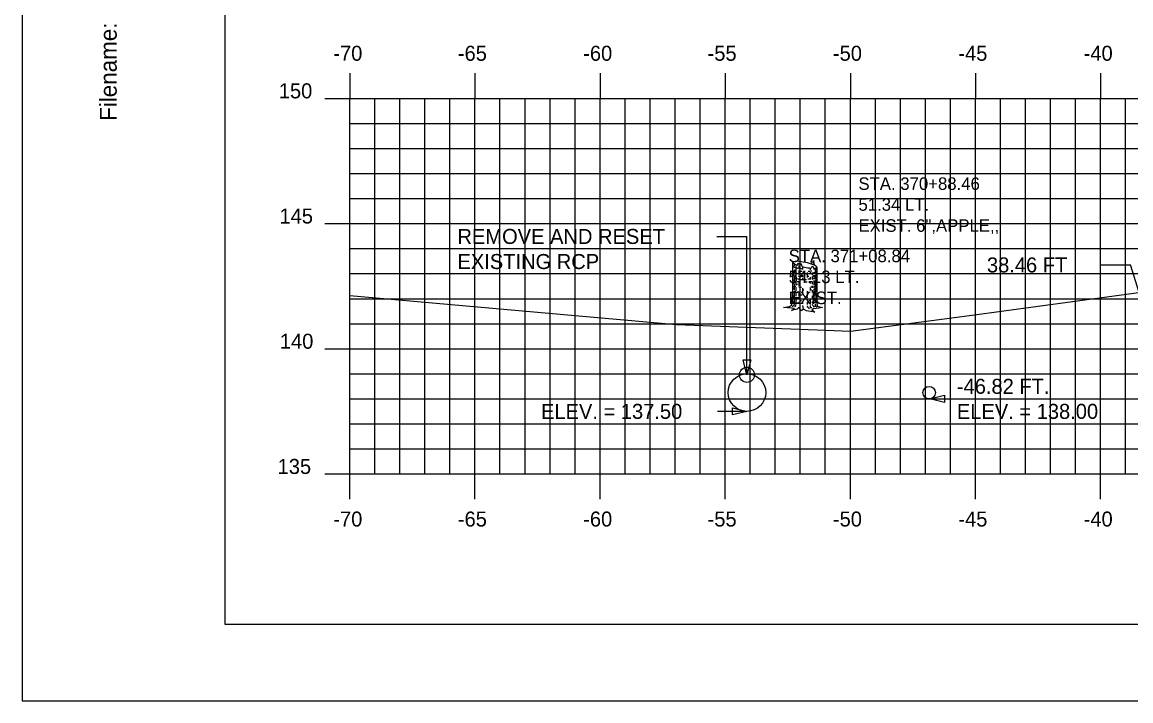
# Model space of a CAD drawing. Extents: x 1148299 to 1148469, y 608981 to 609091.
# Drawn here: x 1148298.63 to 1148342.93, y 608981.28 to 609008.38 of the extents above; entities that cross this region are included whole.
import ezdxf

# ---------------------------------------------------------------- set-up
doc = ezdxf.new("R2010")
doc.units = 0
for name, color, linetype in [('ANNOTATION', 7, 'Continuous'), ('BORDER', 7, 'Continuous'), ('D_Drainage_Culvert', 7, 'Continuous'), ('D_Text_Monospaced', 7, 'Continuous'), ('D_Text_Standard', 7, 'Continuous'), ('H_V ANNOTATION', 7, 'Continuous'), ('MAJOR', 7, 'Continuous'), ('MINOR', 7, 'Continuous'), ('PLOT BOUNDARY', 7, 'Continuous'), ('S_Drainage_Invert', 7, 'Continuous'), ('S_Roadway_Centerline', 7, 'Continuous'), ('S_Trees_Decid_NonPay', 7, 'Continuous')]:
    doc.layers.add(name, color=color, linetype=linetype)

msp = doc.modelspace()

# ---------------------------------------------------------------- linework, layer by layer
at = {"layer": 'ANNOTATION'}
for p, q in [((1148326.393, 608999.82), (1148327.593, 608999.82)), ((1148327.593, 608994.294), (1148327.593, 608999.82)), ((1148341.723, 608998.682), (1148342.923, 608998.682)), ((1148343.264, 608997.583), (1148342.923, 608998.682))]:
    msp.add_line(p, q, dxfattribs=at)
msp.add_lwpolyline([(1148327.743, 608994.894), (1148327.593, 608994.294), (1148327.443, 608994.894)], close=True, dxfattribs=at)
at = {"layer": 'BORDER'}
msp.add_lwpolyline([(1148306.724, 608984.335), (1148466.724, 608984.335), (1148466.724, 609089.335), (1148306.724, 609089.335)], close=True, dxfattribs=at)
at = {"layer": 'D_Drainage_Culvert'}
for centre, radius in [((1148327.593, 608993.585), 0.75), ((1148334.873, 608993.583), 0.25)]:
    msp.add_circle(centre, radius, dxfattribs=at)
at = {"layer": 'D_Text_Standard'}
msp.add_line((1148335.982, 608993.335), (1148340.686, 608993.335), dxfattribs=at)
for points in [[(1148334.904, 608993.335), (1148335.486, 608993.481), (1148335.486, 608993.19)], [(1148327.593, 608992.835), (1148327.011, 608992.69), (1148327.011, 608992.981)]]:
    msp.add_lwpolyline(points, close=True, dxfattribs=at)
for points in [[(1148334.904, 608993.335), (1148335.302, 608993.335), (1148335.982, 608993.335)], [(1148327.593, 608992.835), (1148327.091, 608992.835), (1148326.411, 608992.835)]]:
    msp.add_lwpolyline(points, dxfattribs=at)
at = {"layer": 'MAJOR'}
for p, q in [((1148311.724, 609006.337), (1148311.724, 609005.335)), ((1148316.724, 609006.337), (1148316.724, 609005.335)), ((1148321.724, 609006.337), (1148321.724, 609005.335)), ((1148326.724, 609006.337), (1148326.724, 609005.335)), ((1148331.724, 609006.337), (1148331.724, 609005.335)), ((1148336.724, 609006.337), (1148336.724, 609005.335)), ((1148341.724, 609006.337), (1148341.724, 609005.335)), ((1148310.722, 609005.335), (1148311.724, 609005.335)), ((1148311.724, 609005.335), (1148451.724, 609005.335)), ((1148311.724, 608990.335), (1148311.724, 609005.335)), ((1148311.724, 608990.335), (1148311.724, 609005.335)), ((1148311.724, 609005.335), (1148451.724, 609005.335)), ((1148316.724, 608990.335), (1148316.724, 609005.335)), ((1148321.724, 608990.335), (1148321.724, 609005.335)), ((1148326.724, 608990.335), (1148326.724, 609005.335)), ((1148331.724, 608990.335), (1148331.724, 609005.335)), ((1148336.724, 608990.335), (1148336.724, 609005.335)), ((1148341.724, 608990.335), (1148341.724, 609005.335)), ((1148310.722, 609000.335), (1148311.724, 609000.335)), ((1148311.724, 609000.335), (1148451.724, 609000.335)), ((1148310.722, 608995.335), (1148311.724, 608995.335)), ((1148311.724, 608995.335), (1148451.724, 608995.335)), ((1148310.722, 608990.335), (1148311.724, 608990.335)), ((1148311.724, 608990.335), (1148451.724, 608990.335)), ((1148311.724, 608990.335), (1148451.724, 608990.335)), ((1148311.724, 608989.333), (1148311.724, 608990.335)), ((1148316.724, 608989.333), (1148316.724, 608990.335)), ((1148321.724, 608989.333), (1148321.724, 608990.335)), ((1148326.724, 608989.333), (1148326.724, 608990.335)), ((1148331.724, 608989.333), (1148331.724, 608990.335)), ((1148336.724, 608989.333), (1148336.724, 608990.335)), ((1148341.724, 608989.333), (1148341.724, 608990.335))]:
    msp.add_line(p, q, dxfattribs=at)
at = {"layer": 'MINOR'}
for p, q in [((1148312.724, 608990.335), (1148312.724, 609005.335)), ((1148313.724, 608990.335), (1148313.724, 609005.335)), ((1148314.724, 608990.335), (1148314.724, 609005.335)), ((1148315.724, 608990.335), (1148315.724, 609005.335)), ((1148317.724, 608990.335), (1148317.724, 609005.335)), ((1148318.724, 608990.335), (1148318.724, 609005.335)), ((1148319.724, 608990.335), (1148319.724, 609005.335)), ((1148320.724, 608990.335), (1148320.724, 609005.335)), ((1148322.724, 608990.335), (1148322.724, 609005.335)), ((1148323.724, 608990.335), (1148323.724, 609005.335)), ((1148324.724, 608990.335), (1148324.724, 609005.335)), ((1148325.724, 608990.335), (1148325.724, 609005.335)), ((1148327.724, 608990.335), (1148327.724, 609005.335)), ((1148328.724, 608990.335), (1148328.724, 609005.335)), ((1148329.724, 608990.335), (1148329.724, 609005.335)), ((1148330.724, 608990.335), (1148330.724, 609005.335)), ((1148332.724, 608990.335), (1148332.724, 609005.335)), ((1148333.724, 608990.335), (1148333.724, 609005.335)), ((1148334.724, 608990.335), (1148334.724, 609005.335)), ((1148335.724, 608990.335), (1148335.724, 609005.335)), ((1148337.724, 608990.335), (1148337.724, 609005.335)), ((1148338.724, 608990.335), (1148338.724, 609005.335)), ((1148339.724, 608990.335), (1148339.724, 609005.335)), ((1148340.724, 608990.335), (1148340.724, 609005.335)), ((1148342.724, 608990.335), (1148342.724, 609005.335)), ((1148311.724, 609004.335), (1148451.724, 609004.335)), ((1148311.724, 609004.335), (1148312.726, 609004.335)), ((1148311.724, 609003.335), (1148451.724, 609003.335)), ((1148311.724, 609003.335), (1148312.726, 609003.335)), ((1148311.724, 609002.335), (1148451.724, 609002.335)), ((1148311.724, 609002.335), (1148312.726, 609002.335)), ((1148311.724, 609001.335), (1148451.724, 609001.335)), ((1148311.724, 609001.335), (1148312.726, 609001.335)), ((1148311.724, 608999.335), (1148451.724, 608999.335)), ((1148311.724, 608999.335), (1148312.726, 608999.335)), ((1148311.724, 608998.335), (1148451.724, 608998.335)), ((1148311.724, 608998.335), (1148312.726, 608998.335)), ((1148311.724, 608997.335), (1148451.724, 608997.335)), ((1148311.724, 608997.335), (1148312.726, 608997.335)), ((1148311.724, 608996.335), (1148451.724, 608996.335)), ((1148311.724, 608996.335), (1148312.726, 608996.335)), ((1148311.724, 608994.335), (1148451.724, 608994.335)), ((1148311.724, 608994.335), (1148312.726, 608994.335)), ((1148311.724, 608993.335), (1148451.724, 608993.335)), ((1148311.724, 608993.335), (1148312.726, 608993.335)), ((1148311.724, 608992.335), (1148451.724, 608992.335)), ((1148311.724, 608992.335), (1148312.726, 608992.335)), ((1148311.724, 608991.335), (1148451.724, 608991.335)), ((1148311.724, 608991.335), (1148312.726, 608991.335))]:
    msp.add_line(p, q, dxfattribs=at)
at = {"layer": 'PLOT BOUNDARY'}
msp.add_lwpolyline([(1148298.63, 608981.276), (1148468.63, 608981.276), (1148468.63, 609091.276), (1148298.63, 609091.276)], close=True, dxfattribs=at)
at = {"layer": 'S_Drainage_Invert'}
msp.add_circle((1148327.593, 608994.294), 0.3, dxfattribs=at)
at = {"layer": 'S_Roadway_Centerline'}
msp.add_lwpolyline([(1148311.724, 608997.456), (1148324.779, 608996.299), (1148330.75, 608996.073), (1148331.736, 608996.041), (1148336.482, 608996.659), (1148343.351, 608997.595), (1148346.718, 608997.619), (1148353.827, 608997.677), (1148359.018, 608997.725), (1148361.738, 608997.751), (1148365.941, 608997.793), (1148381.74, 608997.946), (1148386.77, 608997.817), (1148393.486, 608997.801)], dxfattribs=at)
at = {"layer": 'S_Trees_Decid_NonPay'}
for p, q in [((1148329.483, 608998.729), (1148329.483, 608998.634)), ((1148329.67, 608998.659), (1148329.67, 608998.511)), ((1148329.483, 608998.408), (1148329.483, 608998.325)), ((1148329.483, 608998.255), (1148329.483, 608998.004)), ((1148329.551, 608998.642), (1148329.551, 608998.341)), ((1148329.551, 608998.313), (1148329.551, 608998.181)), ((1148329.67, 608998.463), (1148329.67, 608998.294)), ((1148329.817, 608998.613), (1148329.817, 608998.506)), ((1148329.817, 608998.278), (1148329.817, 608998.191)), ((1148329.997, 608998.377), (1148329.997, 608998.177)), ((1148330.114, 608998.561), (1148330.114, 608998.482)), ((1148330.114, 608998.395), (1148330.114, 608998.311)), ((1148330.201, 608998.377), (1148330.201, 608998.29)), ((1148330.201, 608998.22), (1148330.201, 608998.099)), ((1148330.272, 608998.55), (1148330.272, 608998.498)), ((1148330.272, 608998.395), (1148330.272, 608998.313)), ((1148330.272, 608998.278), (1148330.272, 608998.204)), ((1148330.314, 608998.555), (1148330.314, 608998.337)), ((1148330.314, 608998.269), (1148330.314, 608998.117)), ((1148330.341, 608998.485), (1148330.341, 608998.403)), ((1148330.341, 608998.334), (1148330.341, 608998.204)), ((1148329.483, 608997.921), (1148329.483, 608997.691)), ((1148329.551, 608998.147), (1148329.551, 608997.866)), ((1148329.551, 608997.796), (1148329.551, 608997.652)), ((1148329.67, 608997.988), (1148329.67, 608997.839)), ((1148329.817, 608998.156), (1148329.817, 608998.086)), ((1148330.114, 608998.2), (1148330.114, 608998.099)), ((1148330.114, 608998.014), (1148330.114, 608997.938)), ((1148330.201, 608998.023), (1148330.201, 608997.909)), ((1148330.201, 608997.847), (1148330.201, 608997.765)), ((1148330.272, 608998.177), (1148330.272, 608998.117)), ((1148330.272, 608998.064), (1148330.272, 608997.883)), ((1148330.272, 608997.851), (1148330.272, 608997.769)), ((1148330.314, 608998.012), (1148330.314, 608997.934)), ((1148330.314, 608997.907), (1148330.314, 608997.8)), ((1148330.341, 608998.181), (1148330.341, 608998)), ((1148330.341, 608997.952), (1148330.341, 608997.706)), ((1148329.483, 608997.621), (1148329.483, 608997.46)), ((1148329.483, 608997.444), (1148329.483, 608997.339)), ((1148329.551, 608997.582), (1148329.551, 608997.44)), ((1148329.551, 608997.339), (1148329.551, 608997.158)), ((1148329.67, 608997.57), (1148329.67, 608997.417)), ((1148329.817, 608997.753), (1148329.817, 608997.53)), ((1148329.997, 608997.639), (1148329.997, 608997.452)), ((1148329.997, 608997.421), (1148329.997, 608997.368)), ((1148330.114, 608997.753), (1148330.114, 608997.656)), ((1148330.114, 608997.331), (1148330.114, 608997.107)), ((1148330.201, 608997.679), (1148330.201, 608997.582)), ((1148330.201, 608997.452), (1148330.201, 608997.353)), ((1148330.272, 608997.715), (1148330.272, 608997.545)), ((1148330.272, 608997.511), (1148330.272, 608997.232)), ((1148330.314, 608997.765), (1148330.314, 608997.664)), ((1148330.314, 608997.639), (1148330.314, 608997.456)), ((1148330.314, 608997.353), (1148330.314, 608997.162)), ((1148330.341, 608997.687), (1148330.341, 608997.592)), ((1148330.343, 608997.539), (1148330.342, 608997.279)), ((1148329.483, 608997.302), (1148329.483, 608997.178)), ((1148329.551, 608997.098), (1148329.509, 608997.002)), ((1148329.67, 608997.205), (1148329.67, 608997.127)), ((1148329.817, 608997.197), (1148329.817, 608997.131)), ((1148329.857, 608996.911), (1148329.822, 608997.057)), ((1148329.997, 608997.192), (1148329.997, 608997.102)), ((1148330.201, 608997.224), (1148330.201, 608997.166)), ((1148330.272, 608997.179), (1148330.272, 608997.154)), ((1148330.312, 608997.114), (1148330.347, 608997.063)), ((1148330.394, 608996.993), (1148330.327, 608997.024)), ((1148330.341, 608997.24), (1148330.341, 608997.166))]:
    msp.add_line(p, q, dxfattribs=at)
for points in [[(1148330.383, 608998.593), (1148330.383, 608997.181), (1148330.405, 608997.032), (1148330.608, 608996.989), (1148330.469, 608996.954), (1148330.25, 608996.935), (1148330.18, 608996.892), (1148330.302, 608996.803), (1148329.97, 608996.847), (1148329.857, 608996.911), (1148329.764, 608996.851), (1148329.709, 608996.929), (1148329.717, 608996.966), (1148329.656, 608996.968), (1148329.604, 608996.911), (1148329.371, 608996.859), (1148329.499, 608996.948), (1148329.367, 608996.95), (1148329.058, 608996.987), (1148329.297, 608997.018), (1148329.375, 608997.076), (1148329.414, 608997.197), (1148329.431, 608997.551), (1148329.431, 608998.784)], [(1148329.795, 608998.618), (1148329.787, 608998.685), (1148329.762, 608998.69), (1148329.754, 608998.725), (1148329.723, 608998.71), (1148329.709, 608998.725), (1148329.684, 608998.702), (1148329.661, 608998.71), (1148329.649, 608998.759), (1148329.641, 608998.716), (1148329.61, 608998.725), (1148329.607, 608998.673)], [(1148330.287, 608998.673), (1148330.283, 608998.768), (1148330.269, 608998.741), (1148330.269, 608998.862), (1148330.248, 608998.799), (1148330.234, 608998.832), (1148330.217, 608998.776), (1148330.201, 608998.793), (1148330.182, 608998.784), (1148330.163, 608998.717)], [(1148330.265, 608998.549), (1148330.248, 608998.611), (1148330.226, 608998.599), (1148330.195, 608998.634), (1148330.161, 608998.556)], [(1148329.48, 608997.135), (1148329.472, 608997.059), (1148329.394, 608997.009)], [(1148330.005, 608997.053), (1148330.005, 608997.016), (1148330.056, 608996.985), (1148330.073, 608996.935)], [(1148330.117, 608997.059), (1148330.123, 608996.989), (1148330.186, 608996.977)], [(1148330.264, 608997.024), (1148330.221, 608997.059), (1148330.213, 608997.107)], [(1148330.343, 608997.04), (1148330.264, 608997.024), (1148330.248, 608996.981)]]:
    msp.add_lwpolyline(points, dxfattribs=at)
for centre, radius, start, end in [((1148329.449, 608998.784), 0.0179, 168.1723, 184.2278), ((1148329.455, 608998.785), 0.0237, 184.2278, 198.1723), ((1148329.449, 608998.784), 0.0179, 152.1168, 168.1723), ((1148329.454, 608998.782), 0.0237, 138.1723, 152.1168), ((1148329.464, 608998.788), 0.0336, 198.1723, 216.9486), ((1148329.462, 608998.775), 0.0336, 119.396, 138.1723), ((1148329.512, 608998.824), 0.0935, 216.9486, 228.1723), ((1148329.491, 608998.723), 0.0935, 108.1723, 119.396), ((1148329.665, 608998.994), 0.322, 228.1723, 250.2902), ((1148329.562, 608998.506), 0.322, 86.0543, 108.1723), ((1148330.402, 609001.051), 2.507, 250.2902, 251.5281), ((1148329.412, 608996.326), 2.507, 78.1723, 86.0543), ((1148329.412, 608996.326), 2.507, 70.2902, 78.1723), ((1148330.149, 608998.383), 0.322, 48.1723, 70.2902), ((1148329.45, 608998.637), 0.0191, 163.9485, 180), ((1148329.45, 608998.637), 0.0191, 180, 196.0515), ((1148329.456, 608998.639), 0.0252, 196.0515, 210), ((1148329.45, 608998.423), 0.0191, 163.9485, 180), ((1148329.45, 608998.423), 0.0191, 180, 196.0515), ((1148329.456, 608998.425), 0.0252, 196.0515, 210), ((1148329.45, 608998.32), 0.0191, 163.9485, 180), ((1148329.45, 608998.32), 0.0191, 180, 196.0515), ((1148329.456, 608998.322), 0.0252, 196.0515, 210), ((1148329.465, 608998.644), 0.0356, 210, 228.7494), ((1148329.465, 608998.43), 0.0356, 210, 228.7494), ((1148329.465, 608998.327), 0.0356, 210, 228.7494), ((1148329.506, 608998.691), 0.0984, 228.7494, 240), ((1148329.506, 608998.477), 0.0984, 228.7494, 240), ((1148329.506, 608998.374), 0.0984, 228.7494, 240), ((1148329.62, 608998.888), 0.326, 240, 248.3243), ((1148329.62, 608998.674), 0.326, 240, 243.5719), ((1148329.62, 608998.571), 0.326, 240, 243.243), ((1148329.62, 608998.775), 0.326, 240.9099, 257.8036), ((1148329.62, 608998.674), 0.326, 250.4167, 261.8968), ((1148329.62, 608998.571), 0.326, 251.6831, 257.8036), ((1148329.62, 608998.888), 0.326, 257.8036, 261.8968), ((1148329.906, 609000.898), 2.356, 261.8968, 263.2799), ((1148329.906, 609000.684), 2.356, 261.8968, 262.5519), ((1148329.906, 609000.581), 2.356, 263.3413, 264.9946), ((1148329.906, 609000.785), 2.356, 264.242, 267.3673), ((1148329.906, 609000.898), 2.356, 265.24, 267.8386), ((1148329.906, 609000.581), 2.356, 266.5036, 267.8386), ((1148330.402, 609001.051), 2.507, 255.9987, 258.1723), ((1148330.402, 609001.051), 2.507, 258.1723, 264.5013), ((1148329.906, 609000.684), 2.356, 270.8119, 272.1981), ((1148329.906, 609000.581), 2.356, 272.1981, 273.9741), ((1148329.906, 609000.785), 2.356, 273.1481, 276.7734), ((1148329.906, 609000.684), 2.356, 275.0647, 278.1032), ((1148329.906, 609000.581), 2.356, 277.3838, 278.1032), ((1148330.192, 608998.674), 0.326, 278.1032, 279.0854), ((1148330.192, 608998.571), 0.326, 278.1032, 284.0382), ((1148330.251, 608998.871), 0.322, 272.4479, 288.1723), ((1148330.192, 608998.775), 0.326, 291.9506, 300), ((1148330.192, 608998.674), 0.326, 291.9506, 300), ((1148330.322, 608998.654), 0.0935, 288.1723, 299.396), ((1148330.306, 608998.578), 0.0984, 300, 311.2506), ((1148330.306, 608998.477), 0.0984, 300, 311.2506), ((1148330.301, 608998.553), 0.0935, 36.9486, 48.1723), ((1148330.352, 608998.602), 0.0336, 299.396, 318.1723), ((1148330.348, 608998.531), 0.0356, 311.2506, 330), ((1148330.348, 608998.43), 0.0356, 311.2506, 330), ((1148330.349, 608998.589), 0.0336, 18.1723, 36.9486), ((1148330.359, 608998.596), 0.0237, 318.1723, 332.1168), ((1148330.357, 608998.525), 0.0252, 330, 343.9485), ((1148330.357, 608998.425), 0.0252, 330, 343.9485), ((1148330.357, 608998.217), 0.0252, 330, 343.9485), ((1148330.364, 608998.593), 0.0179, 332.1168, 348.1723), ((1148330.359, 608998.592), 0.0237, 4.2278, 18.1723), ((1148330.362, 608998.524), 0.0191, 360, 6.1128), ((1148330.362, 608998.524), 0.0191, 343.9485, 360), ((1148330.362, 608998.423), 0.0191, 360, 6.1128), ((1148330.362, 608998.423), 0.0191, 343.9485, 360), ((1148330.362, 608998.32), 0.0191, 360, 6.1128), ((1148330.362, 608998.32), 0.0191, 343.9485, 360), ((1148330.362, 608998.215), 0.0191, 360, 6.1128), ((1148330.362, 608998.215), 0.0191, 343.9485, 360), ((1148330.364, 608998.593), 0.0179, 348.1723, 4.2278), ((1148329.447, 608997.885), 0.0191, 163.9485, 180), ((1148329.45, 608998.1), 0.0191, 163.9485, 180), ((1148329.45, 608998.1), 0.0191, 180, 196.0515), ((1148329.456, 608998.102), 0.0252, 196.0515, 210), ((1148329.45, 608997.985), 0.0191, 163.9485, 180), ((1148329.45, 608997.985), 0.0191, 180, 196.0515), ((1148329.45, 608997.78), 0.0191, 163.9485, 180), ((1148329.45, 608997.78), 0.0191, 180, 196.0515), ((1148329.456, 608997.782), 0.0252, 196.0515, 210), ((1148329.456, 608997.987), 0.0252, 196.0515, 210), ((1148329.465, 608998.107), 0.0356, 210, 228.7494), ((1148329.465, 608997.787), 0.0356, 210, 228.7494), ((1148329.465, 608997.992), 0.0356, 210, 228.7494), ((1148329.506, 608998.154), 0.0984, 228.7494, 240), ((1148329.507, 608998.04), 0.0984, 228.7494, 240), ((1148329.617, 608998.136), 0.326, 240, 256.9079), ((1148329.62, 608998.351), 0.326, 240, 245.1545), ((1148329.621, 608998.237), 0.326, 240, 247.8656), ((1148329.62, 608998.466), 0.326, 245.1545, 257.8036), ((1148329.621, 608998.237), 0.326, 257.6699, 261.8968), ((1148329.907, 609000.247), 2.356, 261.8968, 262.8615), ((1148329.906, 609000.361), 2.356, 262.6588, 264.7911), ((1148329.906, 609000.476), 2.356, 263.2682, 265.6362), ((1148329.904, 609000.147), 2.356, 264.3443, 266.8529), ((1148329.906, 609000.361), 2.356, 269.5578, 270), ((1148329.906, 609000.361), 2.356, 270, 272.414), ((1148329.906, 609000.476), 2.356, 273.0067, 275.0647), ((1148329.904, 609000.147), 2.356, 274.9734, 277.2455), ((1148329.906, 609000.361), 2.356, 275.0647, 277.1868), ((1148329.906, 609000.476), 2.356, 277.1868, 278.1032), ((1148330.192, 608998.466), 0.326, 278.1032, 284.0382), ((1148330.192, 608998.351), 0.326, 284.0382, 300), ((1148330.193, 608998.237), 0.326, 283.9036, 291.8098), ((1148330.192, 608998.466), 0.326, 291.9506, 300), ((1148330.19, 608998.136), 0.326, 292.4049, 300), ((1148330.193, 608998.237), 0.326, 297.0058, 300), ((1148330.304, 608997.939), 0.0984, 300, 311.2506), ((1148330.306, 608998.269), 0.0984, 300, 311.2506), ((1148330.306, 608998.154), 0.0984, 300, 311.2506), ((1148330.307, 608998.04), 0.0984, 300, 311.2506), ((1148330.345, 608997.892), 0.0356, 311.2506, 330), ((1148330.348, 608998.222), 0.0356, 311.2506, 330), ((1148330.348, 608998.107), 0.0356, 311.2506, 330), ((1148330.348, 608997.787), 0.0356, 311.2506, 330), ((1148330.348, 608997.992), 0.0356, 311.2506, 330), ((1148330.354, 608997.887), 0.0252, 330, 343.9485), ((1148330.357, 608998.102), 0.0252, 330, 343.9485), ((1148330.36, 608997.885), 0.0191, 343.9485, 360), ((1148330.357, 608997.782), 0.0252, 330, 343.9485), ((1148330.357, 608997.987), 0.0252, 330, 343.9485), ((1148330.36, 608997.885), 0.0191, 0, 6.1128), ((1148330.362, 608998.1), 0.0191, 360, 6.1128), ((1148330.362, 608998.1), 0.0191, 343.9485, 360), ((1148330.362, 608997.78), 0.0191, 360, 6.1128), ((1148330.362, 608997.78), 0.0191, 343.9485, 360), ((1148330.363, 608997.985), 0.0191, 0, 6.1128), ((1148330.363, 608997.985), 0.0191, 343.9485, 360), ((1148329.441, 608997.351), 0.0191, 163.9485, 180), ((1148329.441, 608997.351), 0.0191, 180, 196.0515), ((1148329.447, 608997.352), 0.0252, 196.0515, 210), ((1148329.456, 608997.358), 0.0356, 210, 228.7494), ((1148329.446, 608997.461), 0.0191, 163.9485, 180), ((1148329.446, 608997.461), 0.0191, 180, 196.0515), ((1148329.452, 608997.463), 0.0252, 196.0515, 210), ((1148329.461, 608997.468), 0.0356, 210, 228.7494), ((1148329.497, 608997.405), 0.0984, 228.7494, 240), ((1148329.502, 608997.516), 0.0984, 228.7494, 240), ((1148329.506, 608997.835), 0.0984, 228.7494, 240), ((1148329.616, 608997.713), 0.326, 240, 245.9375), ((1148329.62, 608998.032), 0.326, 240, 245.1545), ((1148329.62, 608997.941), 0.326, 241.939, 253.9183), ((1148329.902, 608999.723), 2.356, 262.2226, 264.4852), ((1148329.906, 608999.951), 2.356, 262.5843, 264.4865), ((1148329.906, 608999.838), 2.356, 264.242, 267.469), ((1148329.906, 609000.042), 2.356, 267.8386, 269.0054), ((1148329.906, 608999.951), 2.356, 272.1981, 275.2726), ((1148329.906, 609000.042), 2.356, 275.0647, 276.428), ((1148329.902, 608999.723), 2.356, 277.2863, 278.1032), ((1148330.188, 608997.713), 0.326, 278.1032, 284.7741), ((1148330.192, 608998.032), 0.326, 284.0382, 291.9506), ((1148330.192, 608997.828), 0.326, 284.0382, 291.9506), ((1148330.192, 608998.032), 0.326, 297.1525, 300), ((1148330.302, 608997.516), 0.0984, 300, 311.2506), ((1148330.306, 608997.835), 0.0984, 300, 311.2506), ((1148330.343, 608997.468), 0.0356, 311.2506, 330), ((1148330.352, 608997.463), 0.0252, 330, 343.9485), ((1148330.358, 608997.461), 0.0191, 360, 6.1128), ((1148330.358, 608997.461), 0.0191, 343.9485, 360), ((1148330.362, 608997.69), 0.0191, 360, 6.1128), ((1148329.435, 608997.241), 0.0191, 163.9485, 180), ((1148329.435, 608997.241), 0.0191, 180, 196.0515), ((1148329.441, 608997.242), 0.0252, 196.0515, 210), ((1148329.45, 608997.247), 0.0356, 210, 228.7494), ((1148329.492, 608997.295), 0.0984, 228.7494, 240), ((1148329.605, 608997.492), 0.326, 240, 247.9161), ((1148329.611, 608997.602), 0.326, 240, 241.9097), ((1148329.605, 608997.492), 0.326, 260.3834, 261.8968), ((1148329.892, 608999.502), 2.356, 261.8968, 263.5333), ((1148329.897, 608999.612), 2.356, 264.9089, 266.8158), ((1148329.897, 608999.612), 2.356, 274.1864, 275.2829), ((1148329.892, 608999.502), 2.356, 274.5551, 275.4167), ((1148329.892, 608999.502), 2.356, 277.5403, 278.1032), ((1148330.178, 608997.492), 0.326, 278.1032, 294.7094), ((1148330.183, 608997.602), 0.326, 293.6544, 300), ((1148330.292, 608997.295), 0.0984, 300, 311.2506), ((1148330.333, 608997.247), 0.0356, 311.2506, 330), ((1148330.342, 608997.242), 0.0252, 330, 343.9485), ((1148330.348, 608997.241), 0.0191, 343.9485, 360), ((1148330.348, 608997.241), 0.0191, 0, 6.1128)]:
    msp.add_arc(centre, radius, start, end, dxfattribs=at)

# ---------------------------------------------------------------- texts
at = {"layer": 'ANNOTATION'}
for s, p in [('REMOVE AND RESET ', (1148316.025, 608999.52)), ('EXISTING RCP', (1148316.025, 608998.518)), ('38.46 FT', (1148337.183, 608998.382))]:
    msp.add_text(s, height=0.6, dxfattribs=at).set_placement(p)
at = {"layer": 'BORDER'}
msp.add_text('Filename:', height=0.6696, rotation=90, dxfattribs=at).set_placement((1148302.409, 609004.433))
at = {"layer": 'D_Text_Monospaced'}
for s, height, p in [('STA. 370+88.46', 0.49998, (1148332.049, 609001.679)), ('51.34 LT.', 0.5, (1148332.049, 609000.845)), ('EXIST. 6",APPLE,,', 0.49998, (1148332.049, 609000.005)), ('STA. 371+08.84', 0.49998, (1148329.26, 608998.792)), ('54.13 LT.', 0.5, (1148329.26, 608997.958)), ('EXIST. ', 0.5, (1148329.26, 608997.118))]:
    msp.add_text(s, height=height, dxfattribs=at).set_placement(p)
at = {"layer": 'D_Text_Standard'}
for s, p in [('-46.82 FT.', (1148335.982, 608993.535)), ('ELEV. = 137.50', (1148319.364, 608992.535)), ('ELEV. = 138.00', (1148335.982, 608992.535))]:
    msp.add_text(s, height=0.6, dxfattribs=at).set_placement(p)
at = {"layer": 'H_V ANNOTATION'}
for s, p in [('-70', (1148311.065, 609006.835)), ('-65', (1148316.041, 609006.835)), ('-60', (1148321.049, 609006.835)), ('-55', (1148326.02, 609006.835)), ('-50', (1148331.028, 609006.835)), ('-45', (1148336.041, 609006.835)), ('-40', (1148341.049, 609006.835)), ('150', (1148308.885, 609005.335)), ('145', (1148308.912, 609000.335)), ('140', (1148308.928, 608995.335)), ('135', (1148308.838, 608990.335)), ('-70', (1148311.065, 608988.235)), ('-65', (1148316.041, 608988.235)), ('-60', (1148321.049, 608988.235)), ('-55', (1148326.02, 608988.235)), ('-50', (1148331.028, 608988.235)), ('-45', (1148336.041, 608988.235)), ('-40', (1148341.049, 608988.235))]:
    msp.add_text(s, height=0.6, dxfattribs=at).set_placement(p)
at = {"layer": 'MAJOR'}
msp.add_text('-', height=0.006, dxfattribs=at).set_placement((1148311.719, 608990.335))

doc.saveas('drawing.dxf')
